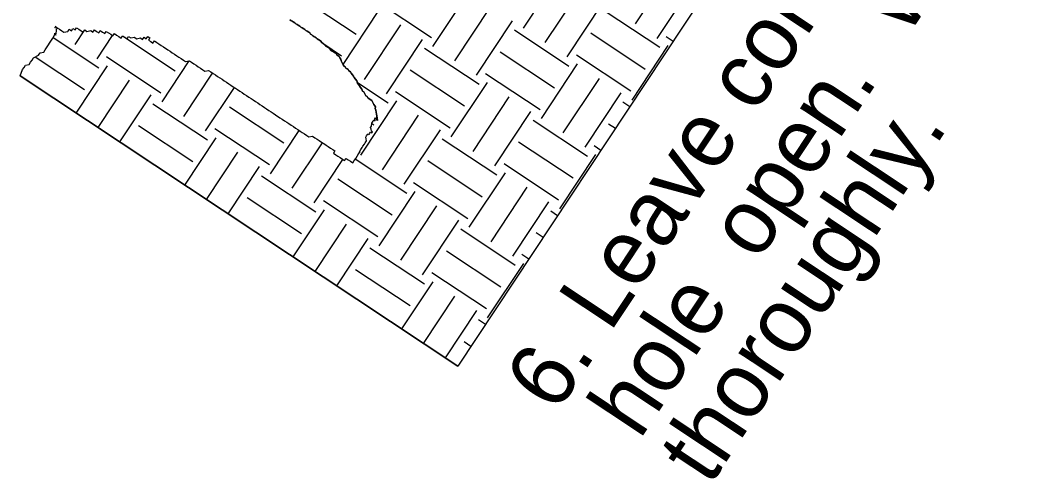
# Model space of a CAD drawing. Extents: x 561231 to 564240, y 590260 to 602519.
# Drawn here: x 563698 to 563755.3, y 590808.8 to 590835.1 of the extents above; entities that cross this region are included whole.
import ezdxf

# ---------------------------------------------------------------- set-up
doc = ezdxf.new("R2010")
doc.units = 0
doc.layers.add('Old_Level_1', color=7, linetype='Continuous')

msp = doc.modelspace()

# ---------------------------------------------------------------- linework, layer by layer
at = {"layer": 'Old_Level_1'}
for p, q in [((563747.362, 590852.299), (563722.914, 590815.443)), ((563726.662, 590834.689), (563728.719, 590837.789)), ((563733.038, 590834.925), (563735.094, 590838.025)), ((563734.278, 590834.102), (563736.334, 590837.202)), ((563721.505, 590833.645), (563723.562, 590836.746)), ((563727.903, 590833.866), (563729.959, 590836.967)), ((563714.025, 590836.408), (563717.125, 590834.351)), ((563718.323, 590836.203), (563721.423, 590834.146)), ((563722.746, 590832.823), (563724.802, 590835.923)), ((563729.143, 590833.044), (563731.199, 590836.144)), ((563716.389, 590832.616), (563718.427, 590835.687)), ((563731.319, 590835.652), (563734.419, 590833.595)), ((563699.967, 590834.686), (563700.022, 590834.768)), ((563717.61, 590831.764), (563719.667, 590834.865)), ((563723.986, 590832), (563726.042, 590835.1)), ((563699.871, 590834.156), (563702.484, 590832.422)), ((563701.139, 590833.761), (563701.682, 590834.58)), ((563702.38, 590832.938), (563703.259, 590834.265)), ((563703.826, 590834.244), (563706.833, 590832.249)), ((563726.147, 590834.585), (563729.247, 590832.528)), ((563730.496, 590834.411), (563733.597, 590832.355)), ((563734.794, 590834.206), (563735.187, 590833.945)), ((563715.286, 590833.785), (563716.303, 590833.111)), ((563718.851, 590830.942), (563720.907, 590834.042)), ((563732.841, 590830.59), (563734.898, 590833.691)), ((563698.856, 590833.043), (563701.661, 590831.182)), ((563702.91, 590833.066), (563706.01, 590831.009)), ((563721.027, 590833.549), (563724.127, 590831.493)), ((563725.324, 590833.344), (563728.424, 590831.288)), ((563729.674, 590833.171), (563732.774, 590831.115)), ((563701.193, 590829.851), (563702.977, 590832.542)), ((563706.078, 590830.485), (563707.628, 590832.822)), ((563727.685, 590829.546), (563729.741, 590832.647)), ((563722.914, 590815.443), (563697.996, 590831.972)), ((563697.996, 590831.972), (563722.914, 590815.443)), ((563722.914, 590815.443), (563697.996, 590831.972)), ((563707.318, 590829.662), (563708.955, 590832.13)), ((563720.204, 590832.309), (563723.304, 590830.253)), ((563724.501, 590832.104), (563727.602, 590830.048)), ((563702.433, 590829.029), (563704.217, 590831.719)), ((563708.558, 590828.84), (563710.195, 590831.307)), ((563717.201, 590831.589), (563718.955, 590830.426)), ((563722.549, 590828.488), (563724.606, 590831.589)), ((563728.925, 590828.724), (563730.981, 590831.824)), ((563703.673, 590828.206), (563705.458, 590830.896)), ((563719.381, 590831.069), (563722.482, 590829.013)), ((563723.79, 590827.666), (563725.846, 590830.766)), ((563730.165, 590827.901), (563732.221, 590831.002)), ((563705.562, 590830.381), (563708.663, 590828.324)), ((563709.912, 590830.207), (563713.012, 590828.151)), ((563717.392, 590827.444), (563719.449, 590830.544)), ((563732.326, 590830.486), (563732.72, 590830.225)), ((563718.633, 590826.622), (563720.689, 590829.722)), ((563725.03, 590826.843), (563727.086, 590829.943)), ((563704.74, 590829.14), (563707.84, 590827.084)), ((563718.019, 590829.261), (563718.132, 590829.186)), ((563727.206, 590829.45), (563730.306, 590827.394)), ((563731.503, 590829.245), (563731.897, 590828.985)), ((563707.372, 590825.752), (563709.157, 590828.442)), ((563709.089, 590828.967), (563712.189, 590826.911)), ((563712.257, 590826.386), (563713.894, 590828.854)), ((563719.873, 590825.799), (563721.929, 590828.9)), ((563713.497, 590825.564), (563715.218, 590828.158)), ((563722.034, 590828.383), (563725.134, 590826.327)), ((563726.383, 590828.21), (563729.483, 590826.154)), ((563730.68, 590828.005), (563731.074, 590827.744)), ((563708.613, 590824.93), (563710.397, 590827.62)), ((563728.728, 590824.389), (563730.785, 590827.49)), ((563709.852, 590824.107), (563711.637, 590826.797)), ((563714.737, 590824.741), (563716.374, 590827.208)), ((563717.083, 590827.236), (563720.014, 590825.292)), ((563721.211, 590827.143), (563724.311, 590825.087)), ((563725.56, 590826.97), (563728.661, 590824.913)), ((563711.741, 590826.281), (563714.842, 590824.225)), ((563723.571, 590823.346), (563725.628, 590826.446)), ((563716.091, 590826.108), (563719.191, 590824.052)), ((563720.388, 590825.903), (563723.488, 590823.847)), ((563724.812, 590822.523), (563726.868, 590825.623)), ((563710.919, 590825.041), (563714.019, 590822.985)), ((563718.436, 590822.287), (563720.493, 590825.388)), ((563715.268, 590824.868), (563718.369, 590822.811)), ((563719.676, 590821.465), (563721.733, 590824.565)), ((563726.052, 590821.7), (563728.108, 590824.801)), ((563713.551, 590821.654), (563715.336, 590824.344)), ((563728.213, 590824.285), (563728.606, 590824.024)), ((563714.791, 590820.831), (563716.576, 590823.521)), ((563720.916, 590820.642), (563722.973, 590823.742)), ((563723.092, 590823.25), (563726.193, 590821.194)), ((563727.39, 590823.045), (563727.784, 590822.784)), ((563716.032, 590820.008), (563717.816, 590822.699)), ((563717.92, 590822.183), (563721.021, 590820.127)), ((563722.27, 590822.01), (563725.371, 590819.953)), ((563726.567, 590821.805), (563726.961, 590821.543)), ((563724.615, 590818.189), (563726.672, 590821.289)), ((563717.098, 590820.943), (563720.198, 590818.887)), ((563721.447, 590820.77), (563724.548, 590818.713)), ((563719.73, 590817.555), (563721.515, 590820.245)), ((563720.97, 590816.732), (563722.755, 590819.423)), ((563722.21, 590815.91), (563723.995, 590818.6)), ((563724.1, 590818.084), (563724.493, 590817.823)), ((563723.277, 590816.844), (563723.671, 590816.583))]:
    msp.add_line(p, q, dxfattribs=at)
for points in [[(563699.986, 590834.791), (563700.114, 590834.707), (563700.24, 590834.623), (563700.367, 590834.539), (563700.494, 590834.455), (563700.705, 590834.498), (563700.789, 590834.625), (563700.916, 590834.541), (563701, 590834.667), (563701.127, 590834.583), (563701.211, 590834.71), (563701.338, 590834.625), (563701.465, 590834.541), (563701.592, 590834.457), (563701.676, 590834.584), (563701.803, 590834.5), (563702.014, 590834.543), (563702.14, 590834.459), (563702.225, 590834.585), (563702.352, 590834.501), (563702.478, 590834.417), (563702.563, 590834.544), (563702.69, 590834.46), (563702.816, 590834.376), (563702.9, 590834.502), (563703.027, 590834.418), (563703.154, 590834.334), (563703.282, 590834.249), (563703.365, 590834.376), (563703.492, 590834.292), (563703.619, 590834.208), (563703.746, 590834.124), (563703.83, 590834.25), (563703.957, 590834.166), (563704.084, 590834.082), (563704.168, 590834.209), (563704.295, 590834.125), (563704.506, 590834.167), (563704.633, 590834.083), (563704.844, 590834.126), (563704.97, 590834.042), (563705.055, 590834.169), (563705.182, 590834.085), (563705.266, 590834.212), (563705.392, 590834.127), (563705.309, 590834.001), (563705.436, 590833.916), (563705.562, 590833.832), (563705.646, 590833.959), (563705.773, 590833.875), (563705.9, 590833.791), (563706.027, 590833.706), (563706.154, 590833.622), (563706.408, 590833.454), (563706.535, 590833.37), (563706.661, 590833.286), (563706.789, 590833.201), (563706.915, 590833.117), (563707.042, 590833.033), (563707.169, 590832.949), (563707.296, 590832.865), (563707.423, 590832.78), (563707.634, 590832.823), (563707.761, 590832.739), (563707.888, 590832.654), (563708.015, 590832.57), (563708.141, 590832.486), (563708.268, 590832.403), (563708.395, 590832.318), (563708.522, 590832.234), (563708.733, 590832.277), (563708.86, 590832.193), (563708.987, 590832.108), (563709.114, 590832.024), (563709.241, 590831.94), (563709.368, 590831.856), (563709.494, 590831.772), (563709.622, 590831.687), (563709.749, 590831.603), (563709.875, 590831.519), (563710.002, 590831.435), (563710.129, 590831.351), (563710.256, 590831.267), (563710.383, 590831.183), (563710.51, 590831.099), (563710.636, 590831.015), (563710.763, 590830.93), (563710.89, 590830.846), (563711.017, 590830.762), (563711.144, 590830.678), (563711.271, 590830.594), (563711.398, 590830.509), (563711.525, 590830.425), (563711.651, 590830.341), (563711.778, 590830.257), (563711.906, 590830.173), (563712.032, 590830.089), (563712.159, 590830.004), (563712.286, 590829.92), (563712.412, 590829.836), (563712.54, 590829.752)], [(563699.986, 590834.791), (563700.114, 590834.707), (563700.24, 590834.623), (563700.367, 590834.539), (563700.494, 590834.455), (563700.705, 590834.498), (563700.789, 590834.625), (563700.916, 590834.541), (563701, 590834.667), (563701.127, 590834.583), (563701.211, 590834.71), (563701.338, 590834.625), (563701.465, 590834.541), (563701.592, 590834.457), (563701.676, 590834.584), (563701.803, 590834.5), (563702.014, 590834.543), (563702.14, 590834.459), (563702.225, 590834.585), (563702.352, 590834.501), (563702.478, 590834.417), (563702.563, 590834.544), (563702.69, 590834.46), (563702.816, 590834.376), (563702.9, 590834.502), (563703.027, 590834.418), (563703.154, 590834.334), (563703.282, 590834.249), (563703.365, 590834.376), (563703.492, 590834.292), (563703.619, 590834.208), (563703.746, 590834.124), (563703.83, 590834.25), (563703.957, 590834.166), (563704.084, 590834.082), (563704.168, 590834.209), (563704.295, 590834.125), (563704.506, 590834.167), (563704.633, 590834.083), (563704.844, 590834.126), (563704.97, 590834.042), (563705.055, 590834.169), (563705.182, 590834.085), (563705.266, 590834.212), (563705.392, 590834.127), (563705.309, 590834.001), (563705.436, 590833.916), (563705.562, 590833.832), (563705.646, 590833.959), (563705.773, 590833.875), (563705.9, 590833.791), (563706.027, 590833.706), (563706.154, 590833.622), (563706.408, 590833.454), (563706.535, 590833.37), (563706.661, 590833.286), (563706.789, 590833.201), (563706.915, 590833.117), (563707.042, 590833.033), (563707.169, 590832.949), (563707.296, 590832.865), (563707.423, 590832.78), (563707.634, 590832.823), (563707.761, 590832.739), (563707.888, 590832.654), (563708.015, 590832.57), (563708.141, 590832.486), (563708.268, 590832.403), (563708.395, 590832.318), (563708.522, 590832.234), (563708.733, 590832.277), (563708.86, 590832.193), (563708.987, 590832.108), (563709.114, 590832.024), (563709.241, 590831.94), (563709.368, 590831.856), (563709.494, 590831.772), (563709.622, 590831.687), (563709.749, 590831.603), (563709.875, 590831.519), (563710.002, 590831.435), (563710.129, 590831.351), (563710.256, 590831.267), (563710.383, 590831.183), (563710.51, 590831.099), (563710.636, 590831.015), (563710.763, 590830.93), (563710.89, 590830.846), (563711.017, 590830.762), (563711.144, 590830.678), (563711.271, 590830.594), (563711.398, 590830.509), (563711.525, 590830.425), (563711.651, 590830.341), (563711.778, 590830.257), (563711.906, 590830.173), (563712.032, 590830.089), (563712.159, 590830.004), (563712.286, 590829.92), (563712.412, 590829.836), (563712.54, 590829.752)], [(563713.353, 590835.168), (563713.416, 590835.126), (563713.48, 590835.084), (563713.543, 590835.042), (563713.638, 590834.979), (563713.702, 590834.937), (563713.765, 590834.895), (563713.828, 590834.853), (563713.923, 590834.789), (563713.987, 590834.747), (563714.051, 590834.705), (563714.145, 590834.642), (563714.209, 590834.6), (563714.273, 590834.558), (563714.336, 590834.516), (563714.431, 590834.453), (563714.495, 590834.41), (563714.537, 590834.337), (563714.601, 590834.295), (563714.664, 590834.253), (563714.727, 590834.211), (563714.791, 590834.169), (563714.854, 590834.127), (563714.918, 590834.085), (563715.013, 590834.022), (563715.108, 590833.959), (563715.182, 590833.863), (563715.278, 590833.8), (563715.32, 590833.726), (563715.383, 590833.684), (563715.446, 590833.642), (563715.51, 590833.6), (563715.574, 590833.558), (563715.637, 590833.516), (563715.711, 590833.421), (563715.774, 590833.379), (563715.838, 590833.338), (563715.933, 590833.274), (563715.997, 590833.232), (563716.039, 590833.158), (563716.103, 590833.116), (563716.167, 590833.074), (563716.208, 590833), (563716.251, 590832.926), (563716.272, 590832.821), (563716.315, 590832.747), (563716.357, 590832.673), (563716.4, 590832.599), (563716.442, 590832.526), (563716.506, 590832.483), (563716.548, 590832.41), (563716.612, 590832.368), (563716.675, 590832.326), (563716.717, 590832.252), (563716.812, 590832.188), (563716.855, 590832.115), (563716.929, 590832.021), (563716.971, 590831.947), (563717.014, 590831.873), (563717.088, 590831.778), (563717.162, 590831.683), (563717.215, 590831.557), (563717.289, 590831.462)], [(563717.289, 590831.462), (563717.215, 590831.557), (563717.162, 590831.683), (563717.088, 590831.778), (563717.014, 590831.873), (563716.971, 590831.947), (563716.929, 590832.021), (563716.855, 590832.115), (563716.812, 590832.188), (563716.717, 590832.252), (563716.675, 590832.326), (563716.612, 590832.368), (563716.548, 590832.41), (563716.506, 590832.483), (563716.442, 590832.526), (563716.4, 590832.599), (563716.357, 590832.673), (563716.315, 590832.747), (563716.272, 590832.821), (563716.251, 590832.926), (563716.208, 590833), (563716.167, 590833.074), (563716.103, 590833.116), (563716.039, 590833.158), (563715.997, 590833.232), (563715.933, 590833.274), (563715.838, 590833.338), (563715.774, 590833.379), (563715.711, 590833.421), (563715.637, 590833.516), (563715.574, 590833.558), (563715.51, 590833.6), (563715.446, 590833.642), (563715.383, 590833.684), (563715.32, 590833.726), (563715.278, 590833.8), (563715.182, 590833.863), (563715.108, 590833.959), (563715.013, 590834.022), (563714.918, 590834.085), (563714.854, 590834.127), (563714.791, 590834.169), (563714.727, 590834.211), (563714.664, 590834.253), (563714.601, 590834.295), (563714.537, 590834.337), (563714.495, 590834.41), (563714.431, 590834.453), (563714.336, 590834.516), (563714.273, 590834.558), (563714.209, 590834.6), (563714.145, 590834.642), (563714.051, 590834.705), (563713.987, 590834.747), (563713.923, 590834.789), (563713.828, 590834.853), (563713.765, 590834.895), (563713.702, 590834.937), (563713.638, 590834.979), (563713.543, 590835.042), (563713.48, 590835.084), (563713.416, 590835.126), (563713.353, 590835.168)], [(563699.863, 590834.109), (563699.971, 590834.322), (563699.982, 590834.407), (563700.035, 590834.28), (563700.066, 590834.534), (563700.077, 590834.618), (563700.119, 590834.681), (563700.114, 590834.707)], [(563697.996, 590831.972), (563698.141, 590832.325), (563698.223, 590832.449), (563698.306, 590832.574), (563698.513, 590832.616), (563698.596, 590832.74), (563698.678, 590832.864), (563698.761, 590832.99), (563699.051, 590833.156), (563699.133, 590833.279), (563699.34, 590833.322), (563699.423, 590833.447), (563699.863, 590834.109)], [(563717.289, 590831.462), (563717.374, 590831.314), (563717.448, 590831.219), (563717.501, 590831.093), (563717.565, 590831.051), (563717.607, 590830.977), (563717.649, 590830.903), (563717.692, 590830.829), (563717.756, 590830.787), (563717.798, 590830.713), (563717.861, 590830.671), (563717.925, 590830.629), (563718.02, 590830.566), (563718.063, 590830.492), (563718.105, 590830.419), (563718.147, 590830.345), (563718.19, 590830.27), (563718.232, 590830.197), (563718.222, 590830.112), (563718.243, 590830.007), (563718.265, 590829.902), (563718.286, 590829.796), (563718.307, 590829.691), (563718.355, 590829.428), (563718.355, 590829.428), (563718.318, 590829.638)], [(563718.318, 590829.638), (563718.355, 590829.428), (563718.355, 590829.428), (563718.307, 590829.691), (563718.286, 590829.796), (563718.265, 590829.902), (563718.243, 590830.007), (563718.222, 590830.112), (563718.232, 590830.197), (563718.19, 590830.27), (563718.147, 590830.345), (563718.105, 590830.419), (563718.063, 590830.492), (563718.02, 590830.566), (563717.925, 590830.629), (563717.861, 590830.671), (563717.798, 590830.713), (563717.756, 590830.787), (563717.692, 590830.829), (563717.649, 590830.903), (563717.607, 590830.977), (563717.565, 590831.051), (563717.501, 590831.093), (563717.448, 590831.219), (563717.374, 590831.314), (563717.289, 590831.462)], [(563712.54, 590829.752), (563712.794, 590829.583), (563712.92, 590829.499), (563713.047, 590829.415), (563713.175, 590829.331), (563713.301, 590829.247), (563713.428, 590829.163), (563713.555, 590829.078), (563713.682, 590828.994), (563713.809, 590828.91), (563713.936, 590828.826), (563714.062, 590828.742), (563714.189, 590828.658), (563714.317, 590828.573), (563714.443, 590828.489), (563714.654, 590828.532), (563714.781, 590828.448), (563714.908, 590828.364), (563715.034, 590828.279), (563715.162, 590828.195), (563715.288, 590828.111), (563715.415, 590828.027), (563715.542, 590827.943), (563715.669, 590827.858), (563715.796, 590827.774), (563715.923, 590827.69), (563715.839, 590827.563), (563715.965, 590827.479), (563716.093, 590827.395), (563716.219, 590827.311), (563716.346, 590827.227), (563716.473, 590827.143), (563716.557, 590827.269), (563716.684, 590827.185), (563716.811, 590827.101), (563716.938, 590827.017), (563717.022, 590827.143), (563717.106, 590827.27), (563717.19, 590827.397), (563717.274, 590827.524), (563717.358, 590827.651)], [(563712.54, 590829.752), (563712.794, 590829.583), (563712.92, 590829.499), (563713.047, 590829.415), (563713.175, 590829.331), (563713.301, 590829.247), (563713.428, 590829.163), (563713.555, 590829.078), (563713.682, 590828.994), (563713.809, 590828.91), (563713.936, 590828.826), (563714.062, 590828.742), (563714.189, 590828.658), (563714.317, 590828.573), (563714.443, 590828.489), (563714.654, 590828.532), (563714.781, 590828.448), (563714.908, 590828.364), (563715.034, 590828.279), (563715.162, 590828.195), (563715.288, 590828.111), (563715.415, 590828.027), (563715.542, 590827.943), (563715.669, 590827.858), (563715.796, 590827.774), (563715.923, 590827.69), (563715.839, 590827.563), (563715.965, 590827.479), (563716.093, 590827.395), (563716.219, 590827.311), (563716.346, 590827.227), (563716.473, 590827.143), (563716.557, 590827.269), (563716.684, 590827.185), (563716.811, 590827.101), (563716.938, 590827.017), (563717.022, 590827.143), (563717.106, 590827.27), (563717.19, 590827.397), (563717.274, 590827.524), (563717.358, 590827.651)], [(563717.274, 590827.524), (563717.39, 590827.767), (563717.432, 590827.831), (563717.474, 590827.894), (563717.516, 590827.957), (563717.6, 590828.084), (563717.642, 590828.147), (563717.685, 590828.211), (563717.726, 590828.274), (563717.705, 590828.38), (563717.684, 590828.485), (563717.726, 590828.548), (563717.768, 590828.612), (563717.81, 590828.676), (563717.873, 590828.634), (563717.915, 590828.697), (563717.957, 590828.761), (563718.021, 590828.718), (563718.063, 590828.781), (563717.999, 590828.824), (563717.979, 590828.929), (563717.957, 590829.034), (563717.998, 590829.098), (563718.02, 590829.267), (563718.103, 590829.394), (563718.146, 590829.457), (563718.209, 590829.415), (563718.188, 590829.52), (563718.23, 590829.583), (563718.355, 590829.428), (563718.355, 590829.428), (563718.23, 590829.583)]]:
    msp.add_lwpolyline(points, dxfattribs=at)

# ---------------------------------------------------------------- texts
for s, p in [('6. Leave compaction ', (563728.529, 590812.689)), (' hole  open.  Water', (563732.516, 590810.045)), (' thoroughly.', (563736.502, 590807.401))]:
    msp.add_text(s, height=3.72047, rotation=56.4424, dxfattribs=at).set_placement(p)

doc.saveas('drawing.dxf')
